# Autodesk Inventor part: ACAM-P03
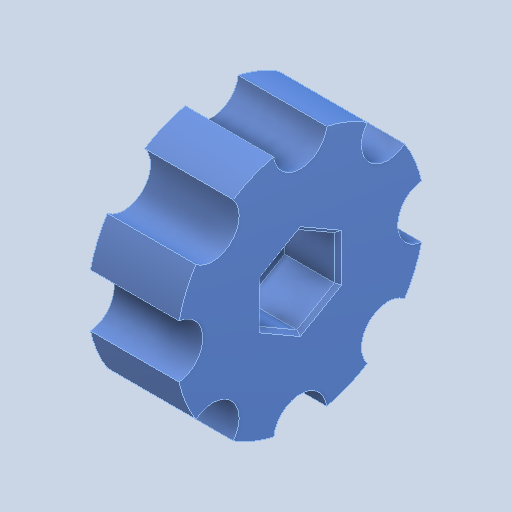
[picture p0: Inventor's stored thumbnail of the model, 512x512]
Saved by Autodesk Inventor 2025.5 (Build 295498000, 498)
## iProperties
Created: 2026-10
Part Number: ACAM-P03
Material: Genérico
Document SubType Name: Modeling
Designer: Luis M
Density: 1 g/cm^3
Appearance: Valor por defecto
Description: Pomo de ajuste M5
Material_BOM: PLA
Proceso_BOM: Impresión 3D
Author: Luis M
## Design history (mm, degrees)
feature "Base1"
node "Sólido1"
